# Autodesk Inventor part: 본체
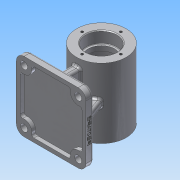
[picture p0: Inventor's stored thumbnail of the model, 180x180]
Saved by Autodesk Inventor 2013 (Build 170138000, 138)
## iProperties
Created: 2019-06
Part Number: 본체
Material: 알루미늄 6061
Document SubType Name: Modeling
Designer: Administrator
Density: 2.71 g/cm^3
Mass: 612.634 g
Surface Area: 622.716 cm^2
Volume: 226.064 cm^3
Author: Administrator
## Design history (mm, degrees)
sketch "스케치2"
  geometry: L1 (0, 45)-(0, 0); L2 (0, 45)-(32, 45); L3 (32, 45)-(32, 0); L4 (32, 0)-(0, 0); L5 (20, 45)-(20, 30); L6 (20, 30)-(17, 30); L7 (17, 30)-(17, 24); L8 (17, 24)-(25, 24); L9 (25, 24)-(25, 0)
  constraints: 18 end point, 6 perpendicular, 4 point on line, 2 parallel, 1 vertical
  dimensions: "d1" = 45 distance of L1.start L1.end; "d3" = 64 diameter of L3 L1; "d4" = 40 diameter of L5 L1; "d5" = 34 diameter of L7 L1; "d6" = 50 diameter of L9 L1; "d7" = 15 distance between parallel lines of L6 L2; "d8" = 24 distance between parallel lines of L4 L8
revolve "회전1" stored, may be unused: angle "d9" = 90 deg
revolve "회전2" stored, may be unused: angle "d10" = 90 deg
node "작업 평면1"
sketch "스케치3"
  geometry: L1 (45, -45)-(-45, -45); L2 (-45, -45)-(-45, 45); L3 (-45, 45)-(45, 45); L4 (45, 45)-(45, -45); L5 (45, -45)-(-45, 45); L6 (-45, -45)-(45, 45); 1 further point
  constraints: 12 end point, 2 midpoint, 2 parallel, 1 horizontal, 1 perpendicular
  dimensions: "d12" = 90 distance of L2.end L3.end; "d13" = 90 distance of L1.end L2.end
extrude "돌출1" join sketch "스케치3" distance "d14" = 10; taper "d15" = 0 deg
node "작업 평면2"
sketch "스케치4"
  geometry: C1 r 5 at (0, 0); 1 further point
  constraints: 1 centre point, 1 coincident
  dimensions: "d17" = 10 diameter of C1
extrude "돌출2" join sketch "스케치4" stored distance "d18" = 10; taper "d19" = 0 deg
hole "구멍1" diameter "d22" = 4.917; stored, may be unused: countersink angle "d26" = 90 deg, drill point angle "d28" = 0 deg; dims "d20" = 10, "d21" = 10, "d23" = 6, "d24" = 4, "d25" = 2, "d27" = 8
sketch "스케치5"
  geometry: C1 r 20 at (0, 0) reference; 1 further point
  constraints: 1 vertical alignment
  dimensions: "d29" = 25 distance of C1.centre point (0, 25)
hole "구멍2" sketch "스케치5" at (0, 25) diameter "d30" = 3.242; stored, may be unused: countersink angle "d34" = 90 deg, drill point angle "d36" = 118 deg; dims "d31" = 7, "d32" = 4, "d33" = 2, "d35" = 9
sketch "스케치6"
  geometry: L1 (5, 35)-(-5, 35); L2 (-5, 35)-(-5, -35); L3 (-5, -35)-(5, -35); L4 (5, -35)-(5, 35); L5 (5, 35)-(-5, -35); L6 (-5, 35)-(5, -35); 1 further point
  constraints: 12 end point, 2 midpoint, 2 parallel, 1 horizontal, 1 perpendicular
  dimensions: "d40" = 10 distance of L3.end L2.end; "d41" = 70 distance of L2.end L1.end
extrude "돌출3" join sketch "스케치6" stored distance "d42" = 10; taper "d43" = 0 deg
sketch "스케치7"
  geometry: L1 (45, -55)-(-45, -55) reference; L2 (-35, -55)-(-26.118, -30.598); L3 (-45, -65)-(-45, -55) reference; 1 further point
  constraints: 2 end point, 1 point on line
  dimensions: "d44" = 10 distance from line of L2.start L3; "d45" = 110 deg angle of L2 L1
feature "리브1" sketch "스케치7" dims "d46" = 1, "d47" = 10, "d48" = 0, "d49" = 0, "d50" = 1, "d51" = 1
fillet "모깎기1" dims "d52" = 10
sketch "스케치9"
  geometry: A1 r 10 centre (35, -35) between (35, -45) and (45, -35) reference; A2 r 10 centre (35, 35) between (45, 35) and (35, 45) reference; A3 r 10 centre (-35, 35) between (-35, 45) and (-45, 35) reference; A4 r 10 centre (-35, -35) between (-45, -35) and (-35, -45) reference; 5 further points
  constraints: 4 coincident
hole "구멍3" sketch "스케치9" at (-35, 35), (-35, -35), (35, -35), (35, 35) diameter "d53" = 9; stored, may be unused: countersink angle "d57" = 90 deg, drill point angle "d59" = 0 deg; dims "d54" = 7, "d55" = 4, "d56" = 2, "d58" = 9
sketch "스케치10"
  geometry: L1 (70, 0)-(0, 0) reference; 2 further points
  constraints: 1 vertical alignment, 1 other
  dimensions: "d60" = 4 distance from line of point (35, 4) L1
feature "엠보싱1" sketch "스케치10" dims "d1" = 45, "d3" = 64, "d4" = 40, "d5" = 34, "d6" = 50, "d7" = 15, "d8" = 24, "d12" = 90, "d13" = 90, "d61" = 0.5, "d62" = 0
fillet "모깎기2" dims "d63" = 2
fillet "모깎기3" dims "d64" = 3
fillet "모깎기4" dims "d65" = 0.6
chamfer "모따기1" distance "d66" = 1; stored, may be unused: second distance "d67" = 2, angle "d68" = 45 deg
sketch "스케치11"
  geometry: L1 (35, 45)-(-35, 45) reference; L2 (-45, 35)-(-45, -35) reference; L3 (-26.34, -40)-(26.34, -40); L4 (40, -26.34)-(40, 26.34); L5 (26.34, 40)-(-26.34, 40); L6 (-40, 26.34)-(-40, -26.34); L7 (-40, -40)-(40, 40); L8 (40, -40)-(-40, 40); A1 r 10 centre (35, 35) between (45, 35) and (35, 45) reference; A2 r 10 centre (-35, 35) between (-35, 45) and (-45, 35) reference; A3 r 10 centre (-35, -35) between (-45, -35) and (-35, -45) reference; A4 r 10 centre (35, -35) between (35, -45) and (45, -35) reference; A5 r 10 centre (-35, 35) between (-40, 26.34) and (-26.34, 40); A6 r 10 centre (-35, -35) between (-26.34, -40) and (-40, -26.34); A7 r 10 centre (35, -35) between (40, -26.34) and (26.34, -40); A8 r 10 centre (35, 35) between (26.34, 40) and (40, 26.34); 1 further point
  constraints: 12 end point, 8 point on circle, 4 centre point, 4 coincident, 2 midpoint, 2 parallel, 1 horizontal, 1 perpendicular
  dimensions: "d69" = 20 diameter of A5; "d71" = 20 diameter of A6; "d72" = 20 diameter of A7; "d73" = 20 diameter of A8; "d76" = 80 distance between parallel lines of L6 L4; "d77" = 80 distance between parallel lines of L5 L3; "d78" = 5 distance between parallel lines of L5 L1; "d79" = 5 distance between parallel lines of L2 L6
extrude "돌출4" cut sketch "스케치11" distance "d80" = 5; taper "d81" = 0 deg
fillet "모깎기5" dims "d82" = 3
fillet "모깎기6" dims "d83" = 3
fillet "모깎기7" dims "d84" = 3
fillet "모깎기8" dims "d85" = 3
fillet "모깎기9" dims "d86" = 3
fillet "모깎기10" dims "d87" = 3
node "솔리드1"
mirror "대칭1"
pattern_circular "원형 패턴1" dims angle "d38" = 360 deg
mirror "대칭2"
mirror "대칭3"
other parameters: "d11" = -65
